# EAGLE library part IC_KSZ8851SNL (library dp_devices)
Fast Ethernet Controller with PHY, MAC and SPI
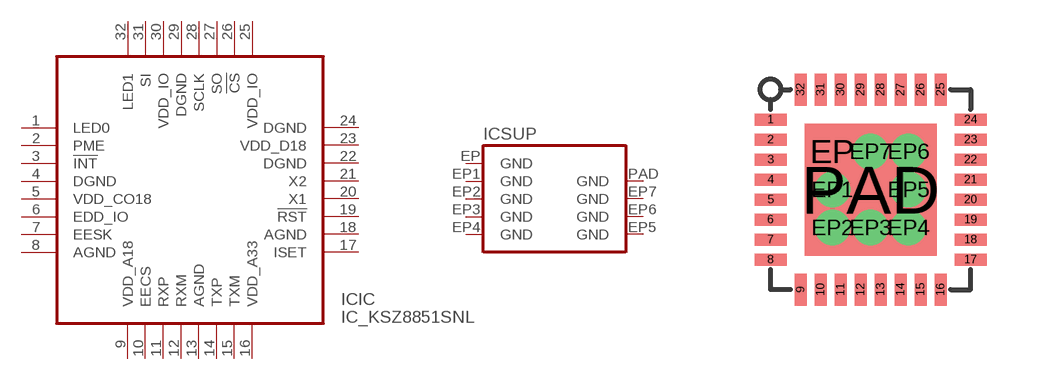
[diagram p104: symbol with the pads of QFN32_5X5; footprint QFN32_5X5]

Designator prefix IC; gates IC=IC_KSZ8851SNL SUP=QFN25_GND

## IC_KSZ8851SNL  [QFN32_5X5]
1  IC:LED0
2  IC:PME
3  IC:!INT
4  IC:DGND  sup
5  IC:VDD_CO18
6  IC:EDD_IO
7  IC:EESK
8  IC:AGND
9  IC:VDD_A18
10  IC:EECS
11  IC:RXP
12  IC:RXM
13  IC:AGND
14  IC:TXP
15  IC:TXM
16  IC:VDD_A33
17  IC:ISET
18  IC:AGND  sup
19  IC:!RST
20  IC:X1
21  IC:X2
22  IC:DGND
23  IC:VDD_D18  sup
24  IC:DGND
25  IC:VDD_IO
26  IC:!CS
27  IC:SO
28  IC:SCLK
29  IC:DGND
30  IC:VDD_IO
31  IC:SI
32  IC:LED1
EP  SUP:GND  sup
EP1  SUP:GND  sup
EP2  SUP:GND  sup
EP3  SUP:GND  sup
EP4  SUP:GND  sup
EP5  SUP:GND  sup
EP6  SUP:GND  sup
EP7  SUP:GND  sup
PAD  SUP:GND  sup

## Footprint QFN32_5X5 (pad centres in mm)
smd 0.8 x 0.3: 1 -2.5,1.75; 2 -2.5,1.25; 3 -2.5,0.75; 4 -2.5,0.25; 5 -2.5,-0.25; 6 -2.5,-0.75; 7 -2.5,-1.25; 8 -2.5,-1.75; 17 2.5,-1.75; 18 2.5,-1.25; 19 2.5,-0.75; 20 2.5,-0.25; 21 2.5,0.25; 22 2.5,0.75; 23 2.5,1.25; 24 2.5,1.75
smd 0.3 x 0.8: 9 -1.75,-2.5; 10 -1.25,-2.5; 11 -0.75,-2.5; 12 -0.25,-2.5; 13 0.25,-2.5; 14 0.75,-2.5; 15 1.25,-2.5; 16 1.75,-2.5; 25 1.75,2.5; 26 1.25,2.5; 27 0.75,2.5; 28 0.25,2.5; 29 -0.25,2.5; 30 -0.75,2.5; 31 -1.25,2.5; 32 -1.75,2.5
drill 0.381 round: EP -0.953,0.953; EP1 -0.953,0; EP2 -0.953,-0.953; EP3 0,-0.953; EP4 0.953,-0.953; EP5 0.953,0; EP6 0.953,0.953; EP7 0,0.953
smd 3.3 x 3.3: PAD 0,0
